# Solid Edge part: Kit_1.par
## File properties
Last saved by: ahadarics
Revision: 76
Dokumentum tartalom típus: 0
Sűrűség: 0,000 kg/m^3
Pontosság: 0,990
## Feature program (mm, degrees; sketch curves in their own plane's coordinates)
base feature "unnamed BaseFeature 1"
sketch for "unnamed Hole 1" plane through (-23.25, -23.25, 90) normal (0, 0, 1) x-axis (0, 1, 0)
  hole centre (0, 0) bore radius 3.3235
hole "unnamed Hole 1" through
sketch for "unnamed Hole 2" plane through (-23.25, -23.25, 90) normal (0, 0, 1) x-axis (0, 1, 0)
  hole centre (46.5, 0) bore radius 3.3235
hole "unnamed Hole 2" through
sketch for "unnamed Hole 3" plane through (-23.25, -23.25, 90) normal (0, 0, 1) x-axis (0, 1, 0)
  hole centre (46.5, -46.5) bore radius 3.3235
hole "unnamed Hole 3" through
sketch for "unnamed Hole 4" plane through (-23.25, -23.25, 90) normal (0, 0, 1) x-axis (0, 1, 0)
  hole centre (0, -46.5) bore radius 3.3235
hole "unnamed Hole 4" through
pattern "unnamed Pattern 1" of "unnamed Hole 1", "unnamed Hole 2", "unnamed Hole 3", "unnamed Hole 4"
thread "unnamed Thread 1"
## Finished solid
Body 1: solid body, 320 faces, 751 edges, 450 vertices, 4 internal voids.
  Faces by surface: plane 141, cylinder 83, swept 53, torus 22, cone 20, spline 1
  Edges by curve: line 413, circle 177, spline 122, ellipse 28, curve on surface 10, intersection 1
Bounding box of the edges (mm; curved faces can reach further): 65.500 x 65.500 x 14.500, from (-32.75, -32.75, 80.5) to (32.75, 32.75, 95).
Cylindrical faces by radius (mm): R0.2 x40, R0.201 x2, R0.2012 x2, R1.75 x1, R2.5402 x12, R2.6 x4, R3.3235 x4, R3.75 x4, R3.85 x4, R4.283 x1, R5.25 x4, R8.27 x1, R8.85 x1, R9 x1, R10.25 x1, R15.5811 x1
Conical faces (half-angle, radius in mm at the cone's reference point): 0.5 deg R6.5 x2, 0.5 deg R8 x4, 7 deg R9.5925 x1, 14 deg R8.135 x1, 14 deg R8.4811 x1, 17 deg R8.135 x1, 23 deg R8.829 x1, 42.5 deg R8.1233 x1, 45 deg R3.6735 x4, 45 deg R9 x1, 84 deg R8.4608 x1, 85 deg R9.9462 x1, 87 deg R8.1765 x1
Toroidal faces (ring radius, tube radius in mm): R2.9402 r0.4 x12, R3.55 r0.2 x8, R8.8057 r0.2025 x1, R9.2522 r0.2925 x1
Planar faces by outward normal: +x 12, +y 12, +z 24, -x 14, -y 12, -z 1, oblique 66
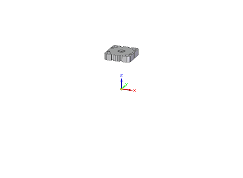
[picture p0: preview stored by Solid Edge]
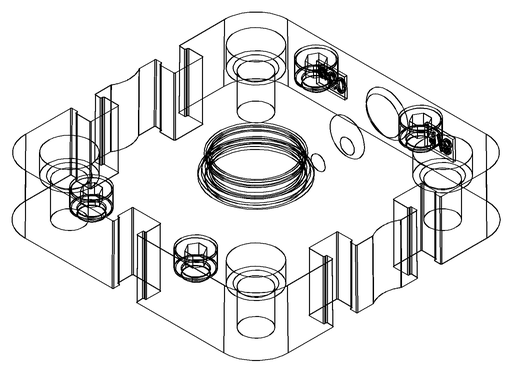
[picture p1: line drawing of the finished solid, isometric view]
